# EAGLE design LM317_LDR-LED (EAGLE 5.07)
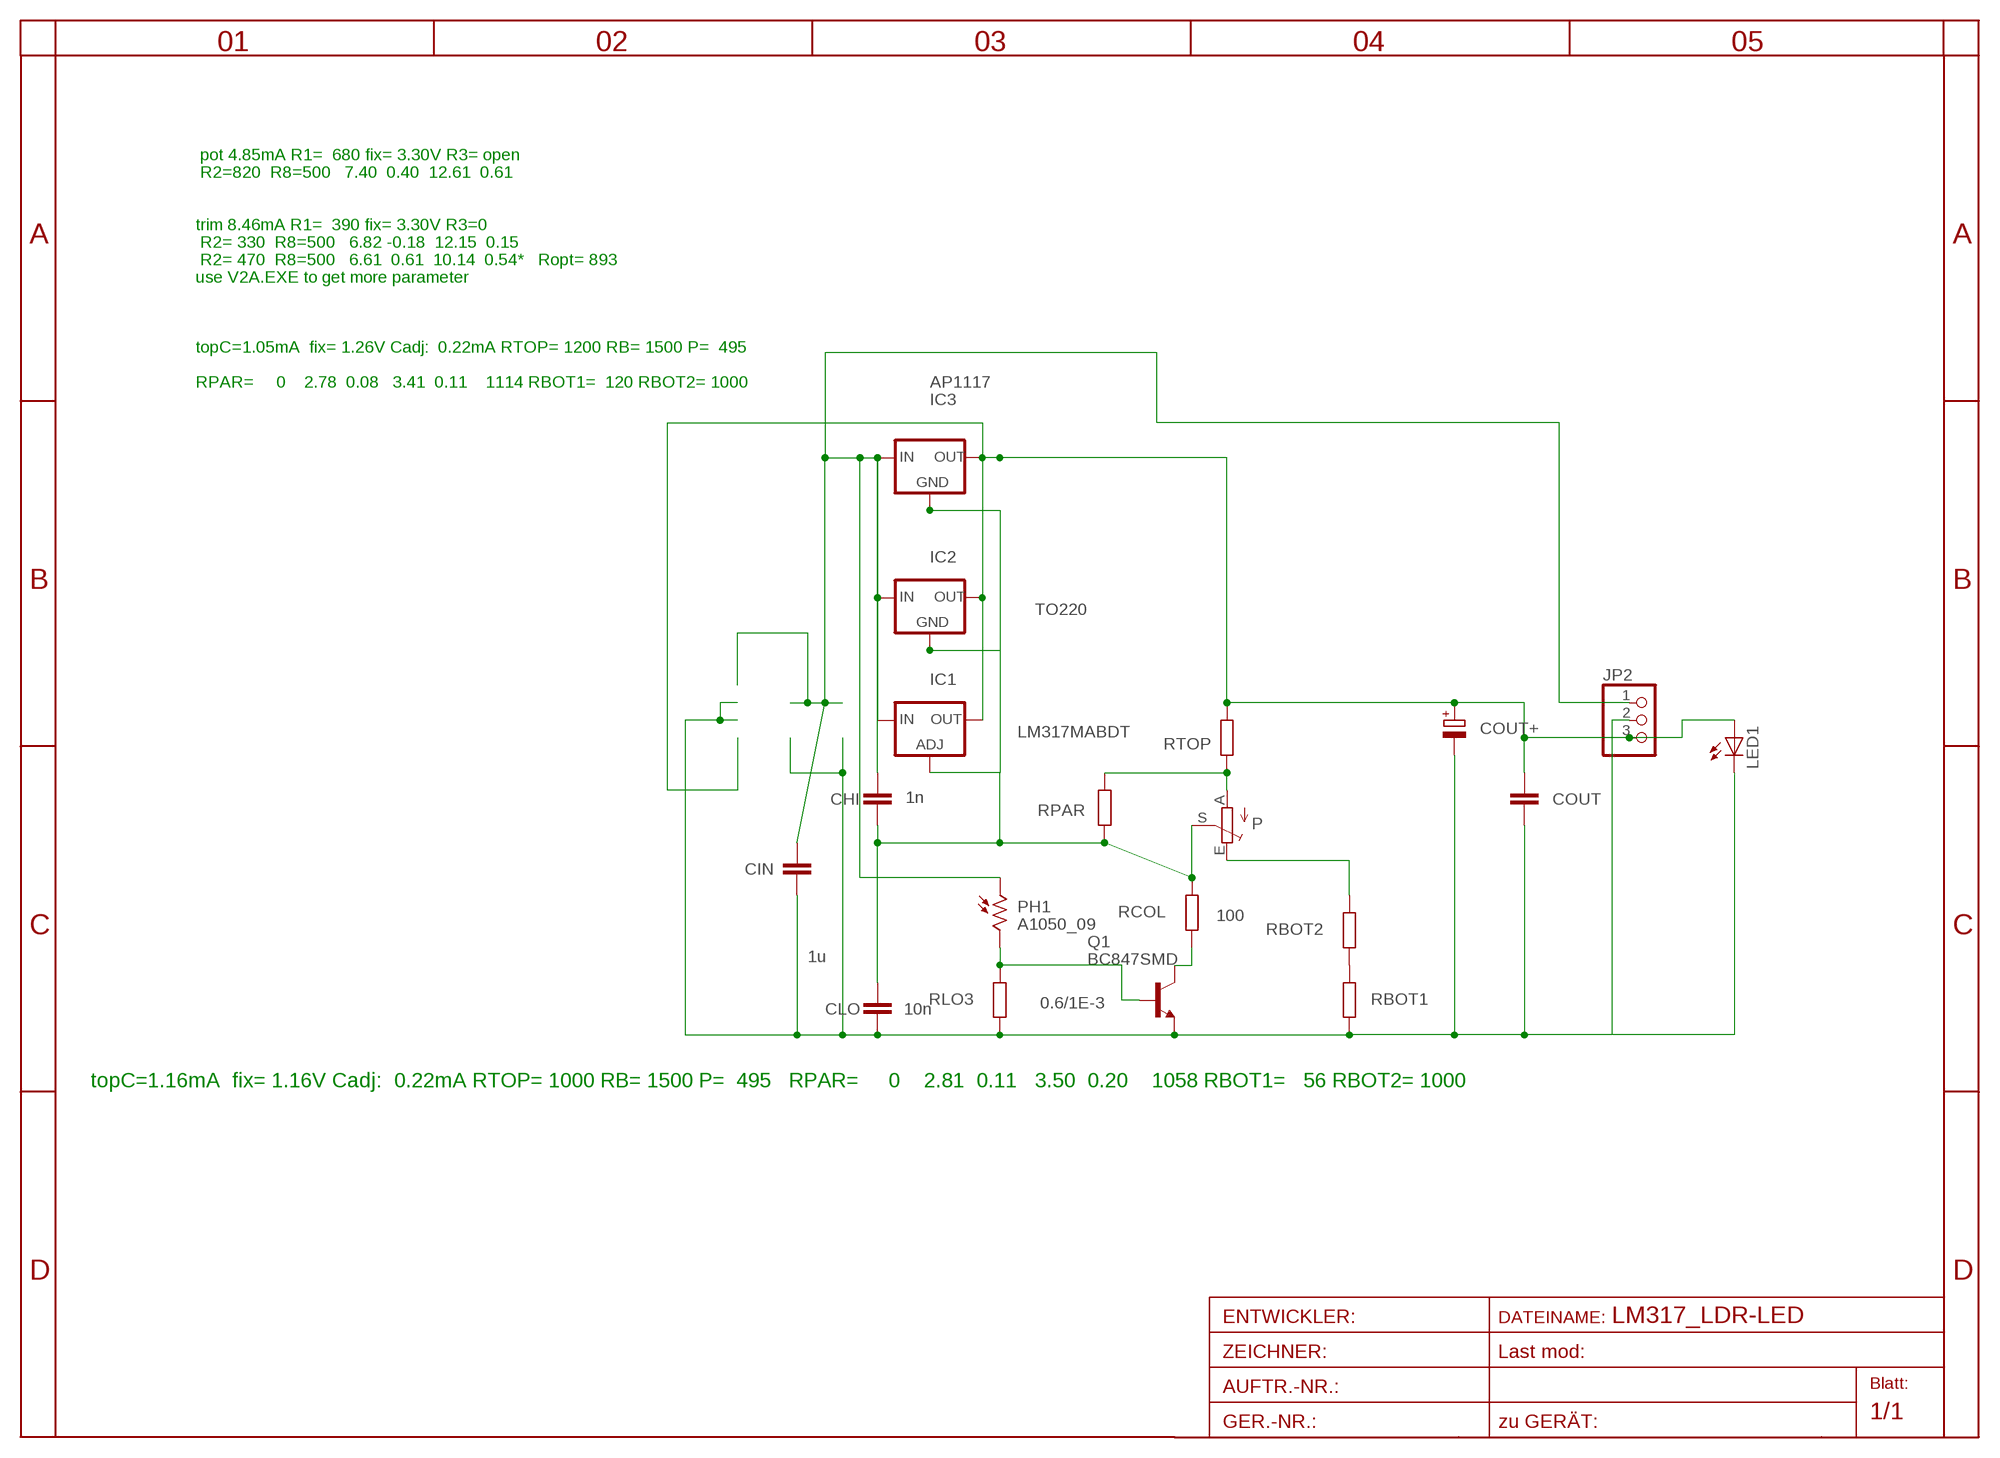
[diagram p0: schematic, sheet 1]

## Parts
CHI  1n  C-EUC0805  [C0805]
CIN  1u  C-EUC1206  [C1206]
CLO  10n  C-EUC0805  [C0805]
COUT  C-EUC1206  [C1206]
COUT+  CPOL-EUE2.5-6  [E2,5-6]
IC1  LM317MABDT  [DPACK]
IC2  TO220  78XXS  [78XXS]
IC3  AP1117  [SOT223]
JP2  PINHD-1X3  [1X03]
LED1  LED1W_HOLE  [1W]
P  TRIM_EU-RAND160  [RANDL]
PH1  A1050_09  [T0-46-A10XX]
Q1  BC847SMD  [SOT23]
RBOT1  R-EU_R0805  [R0805]
RBOT2  R-EU_R0805  [R0805]
RCOL  100  R-EU_R0805  [R0805]
RLO3  0.6/1E-3  R-EU_R0805  [R0805]
RPAR  R-EU_R0805  [R0805]
RTOP  R-EU_R0805  [R0805]

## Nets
GND: CIN.2 CLO.2 COUT+.- COUT.2 JP2.2 LED1.C Q1.2(E) RBOT1.1 RLO3.1
IN: CHI.1 CIN.1 IC1.3(IN) IC2.IN IC3.3(IN) JP2.1 PH1.1
N$1: P.E RBOT2.2
N$2: RBOT1.2 RBOT2.1
N$3: Q1.3(C) RCOL.1
N$4: CHI.2 CLO.1 IC1.1(ADJ) IC2.GND IC3.1(GND) P.S RCOL.2 RPAR.1
N$5: PH1.2 Q1.1(B) RLO3.2
N$7: P.A RPAR.2 RTOP.1
OUT: COUT+.+ COUT.1 IC1.4(OUT) IC2.OUT IC3.2(OUT) IC3.4(TAB) JP2.3 LED1.A RTOP.2

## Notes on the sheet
- pot 4.85mA R1=  680 fix= 3.30V R3= open
- R2=820  R8=500   7.40  0.40  12.61  0.61
- trim 8.46mA R1=  390 fix= 3.30V R3=0
- R2= 330  R8=500   6.82 -0.18  12.15  0.15
- R2= 470  R8=500   6.61  0.61  10.14  0.54*   Ropt= 893
- use V2A.EXE to get more parameter
- topC=1.05mA  fix= 1.26V Cadj:  0.22mA RTOP= 1200 RB= 1500 P=  495
- RPAR=     0    2.78  0.08   3.41  0.11    1114 RBOT1=  120 RBOT2= 1000
- topC=1.16mA  fix= 1.16V Cadj:  0.22mA RTOP= 1000 RB= 1500 P=  495   RPAR=     0    2.81  0.11   3.50  0.20    1058 RBOT1=   56 RBOT2= 1000

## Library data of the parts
CHI CIN CLO COUT = rcl:C-EU: CAPACITOR, European symbol
COUT+ = rcl:CPOL-EU: POLARIZED CAPACITOR, European symbol
IC1 = v-reg:LM317?*: 500 mA Adjustable Output Positive Voltage Regulator Source: http://www.onsemi.co.jp .. LM317M-D.PDF
IC2 = v-reg:78XXS: VOLTAGE REGULATOR
IC3 = v-reg:AP1117
JP2 = pinhead:PINHD-1X3: PIN HEADER
LED1 = led:LED: LED
P = pot:TRIM_EU-: POTENTIOMETER
PH1 = photo-elements:A10: Sensor Robust Light Sensing Applications
Q1 = transistor-npn:BC847*: NPN Transistor
RBOT1 RBOT2 RCOL RLO3 RPAR RTOP = rcl:R-EU_: RESISTOR, European symbol

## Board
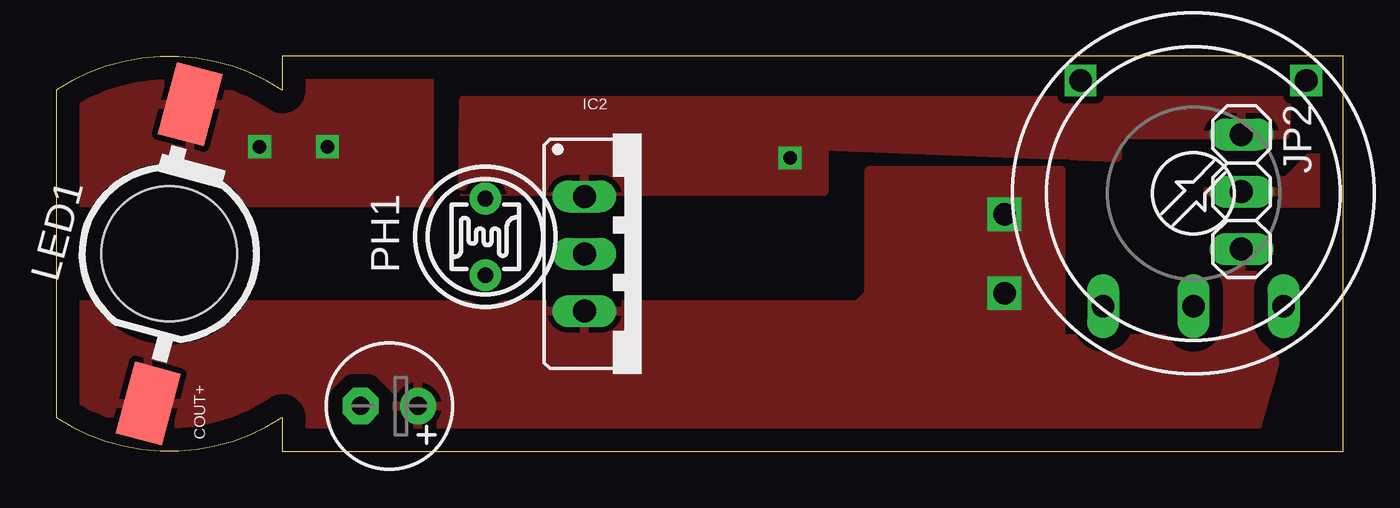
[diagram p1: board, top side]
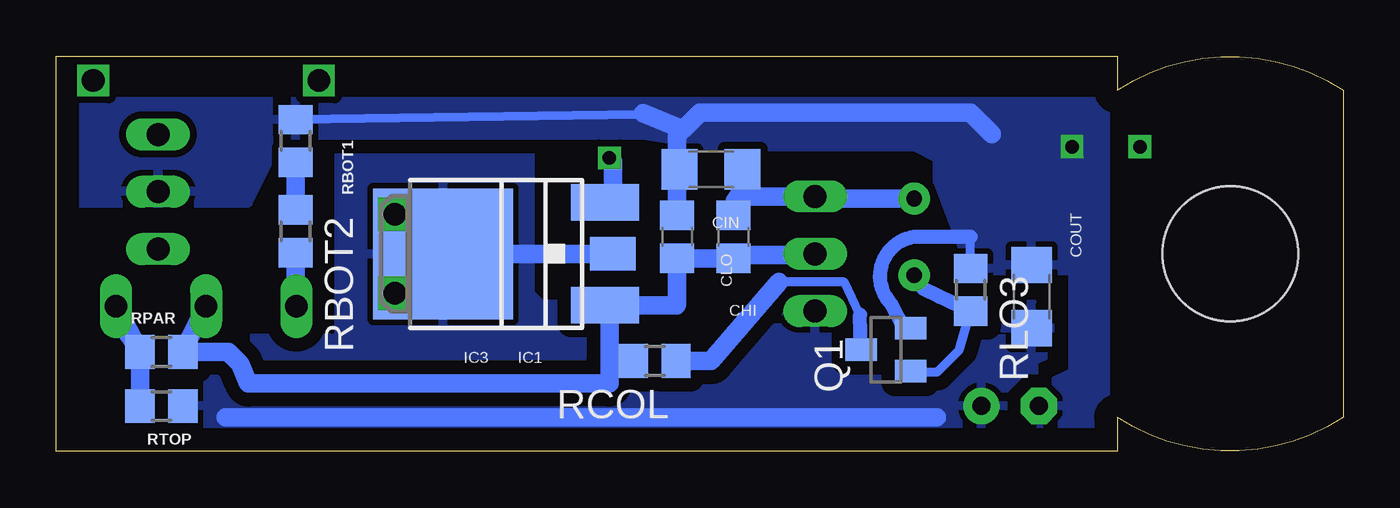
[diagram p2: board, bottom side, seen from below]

Size 57 x 17.5 mm. Coordinates in mm from the lower left corner, seen from the top.
Outline: 0,1.5 arc67 10,1.5 10,0 57,0 57,17.5 10,17.5 10,16 arc67 0,16 0,1.5
Copper layers (1*16): Top 0.035mm / dielectric 1.5mm / Bottom 0.035mm
Design rules "default *": minimum track width 10mil, minimum drill 20mil, track to track 8mil, track to pad 8mil, pad to pad 8mil, via to via 8mil, smd to smd 8mil, copper to edge 40mil, drill to drill 8mil, minimum pad ring 8mil, minimum via ring 8mil, stop-mask expansion 8mil, vias tented up to drill 0mil, thermal gap 10mil

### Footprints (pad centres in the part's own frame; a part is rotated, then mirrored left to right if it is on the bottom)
C0805 = smd 1.3 x 1.5: 1 -0.95,0; 2 0.95,0
C1206 = smd 1.6 x 1.8: 1 -1.4,0; 2 1.4,0
E2,5-6 = drill 0.8 pad 1.6 round: + -1.27,0 | drill 0.8 pad 1.6 octagon: - 1.27,0
DPACK = smd 1.6 x 3: 1 -2.28,-4.8; 3 2.28,-4.8 | smd 5.8 x 6.2: 4 0,2.38
78XXS = drill 1.016 long: GND 0,-2.54; IN -2.54,-2.54; OUT 2.54,-2.54
SOT223 = smd 1.5 x 2: 1 -2.3,-3.15; 2 0,-3.15; 3 2.3,-3.15 | smd 3.8 x 2: 4 0,3.15
1X03 = drill 1.016 long: 1 -2.54,0; 2 0,0; 3 2.54,0
1W = smd 3.3 x 2.1: A -6.65,-0.82; C 6.65,0.82 | hole 6: 0,0
RANDL = drill 1 long: A -4,5; E 4,5; S 0,5 | drill 1 square: P$1 -5,-5; P$2 5,-5
T0-46-A10XX = drill 0.7 pad 1.4 round: 1 -1.7,0; 2 1.7,0
SOT23 = smd 1 x 1.4: 1 -0.95,-1.1; 2 0.95,-1.1; 3 0,1.1
R0805 = smd 1.3 x 1.5: 1 -0.95,0; 2 0.95,0

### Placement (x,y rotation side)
CHI  27,9.5 270 bottom
CIN  28,12.5 180 bottom
CLO  29.5,9.5 90 bottom
COUT  13.8,6.85 90 bottom
COUT+  14.75,2 180 top
IC1  37.5,8.75 90 bottom
IC2  25.93,8.75 270 top
IC3  35.5,8.75 90 bottom
JP2  52.5,11.5 270 top
LED1  5,8.75 75 top
P  50.37,11.43 180 top
PH1  19,9.5 270 top
Q1  20.25,4.5 90 bottom
RBOT1  46.4,13.75 270 bottom
RBOT2  46.4,9.75 270 bottom
RCOL  30.5,4 180 bottom
RLO3  16.5,7.15 270 bottom
RPAR  52.35,4.4 180 bottom
RTOP  52.35,2 0 bottom

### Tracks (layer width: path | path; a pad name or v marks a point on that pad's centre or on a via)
GND  (via drill 0.6)
  Bottom 0.406: RBOT1.1 31.06,14.92 31.01,14.97 | 19.45,5.45 Q1.2 | RLO3.1 16.5,9.5
  Bottom 0.61: 19.45,5.45 20,6.5 arc127 19,9.5 16.5,9.5
  Bottom 0.813: 29.5,12.6 CLO.2 | 15.55,14.05 16.5,15 28.5,15 29.25,14.25 | 29.25,14.25 29.5,14 29.5,12.6 | 29.5,12.6 CIN.2 | 29.25,14.25 31.01,14.97
  other vias: 12,13.5 9,13.5
  pour Bottom (isolate 0.305): 10.5,0.5 10.5,15.5 64.5,15.5 66.5,11 48.5,11 47.5,13 47.5,14 31,14 28.1,13.55 27,13.5 19,13.5 18,13 18,12 16.5,8 12,8 12,3.5 13,3 13.5,0.5
  pour Top: 54.5,12 51,12 51,11 66,11 66,17 60.5,17 60.5,14 59.5,13 55.5,13
  pour Top: 0.5,17 16.5,17 16.5,11 0.5,11
IN  (via drill 0.6)
  Bottom 0.406: IC1.3 32.35,11.03 IC3.3 | 26.31,11.29 26.7,11.5 | 23.3,11.2 IC2.IN
  Bottom 0.813: CIN.1 26.7,11.5 26.95,11.1 CHI.1 | IC3.3 32.35,12.85 v32.5,13 | IC2.IN 26.31,11.29 | PH1.1 23.3,11.2
  pour Top (isolate 0.305, rank 2): 18.04,15.56 54.5,15.56 54.5,15.5 54.44,14 47,14 47,13 34,13.5 34,11.5 18,11.5
N$1
  Bottom 0.813: RBOT2.2 46.4,6.46 P.E
N$2
  Bottom 0.813: RBOT2.1 RBOT1.2
N$3
  Bottom 0.406: 21.4,6.05 22.1,7.5 25,7.5
  Bottom 0.61: Q1.3 21.4,6.05
  Bottom 0.813: 25,7.5 28,4 RCOL.1
N$4
  Bottom 0.406: IC1.1 32.35,6.47 IC3.1 | IC2.GND 24.25,8.75 24.5,8.7 | 26.45,8.7 CHI.2 | 32.5,4 RCOL.2
  Bottom 0.813: CHI.2 CLO.1 29.5,6.5 29.53,6.47 IC1.1 | IC3.1 32.5,6.3 32.5,4 32.5,3 48.5,3 48.87,3.87 49.4,4.4 RPAR.1 50.4,6.4 P.S | 24.5,8.7 26.45,8.7
N$5
  Bottom 0.406: PH1.2 19,7.5 18.6,7.2 | RLO3.2 17,4.5 18,3.5 19.1,3.5 Q1.1
  Bottom 0.61: 18.6,7.2 17.9,6.85 RLO3.2
N$7
  Bottom 0.813: RPAR.2 54.34,6.4 P.A | RPAR.2 54.2,5.72 | RTOP.1 RPAR.2
OUT  (via drill 1)
  Bottom 0.406: IC1.4 42,8.75 v42,7
  Bottom 0.813: IC1.4 39.5,8.37 39.03,8.37 IC3.4 IC3.2 | 18,1.5 49.5,1.5
  other vias: 42,10.5
  pour Bottom (isolate 0.61, rank 2): 36,14 44.5,14 44.5,5 51,5 51,0.5 12.5,0.5 12.5,6.5 35.5,6.5 36,7
  pour Top (isolate 0.61): 36,12.45 44.5,12.45 44.5,5 51.5,5 51.5,9.5 53.5,9.5 53.5,4.5 54,4 53,0.5 0.5,1 1,6.5 35.5,6.5 36,7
